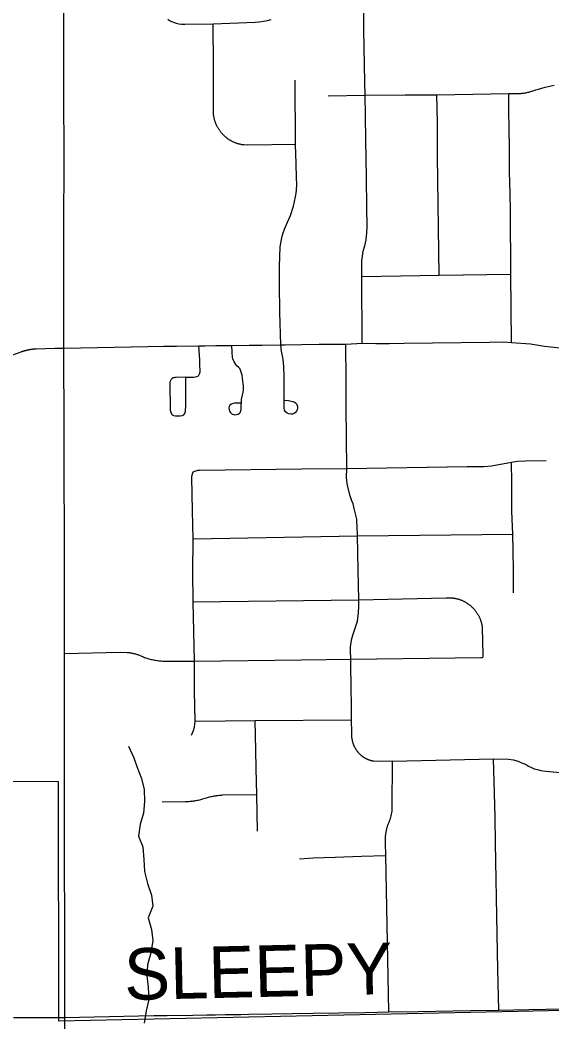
# Model space of a CAD drawing. Extents: x 0 to 34, y 0 to 22.
# Drawn here: x 5.217 to 5.51, y 18.387 to 18.939 of the extents above; entities that cross this region are included whole.
import ezdxf

# ---------------------------------------------------------------- set-up
doc = ezdxf.new("R2010")
doc.units = 0
for name, color, linetype in [('GM_X_City_Street', 7, 'Continuous'), ('GM_X_Corporation', 7, 'Continuous'), ('GM_X_County_Road', 7, 'Continuous'), ('GM_X_County_Road_Text', 7, 'Continuous'), ('GM_X_Minor_River', 7, 'Continuous'), ('GM_X_Township_Road', 7, 'Continuous'), ('GM_X_US_Route', 7, 'Continuous')]:
    doc.layers.add(name, color=color, linetype=linetype)

msp = doc.modelspace()

# ---------------------------------------------------------------- linework, layer by layer
at = {"layer": 'GM_X_City_Street'}
for points in [[(5.40551, 18.76131), (5.40524, 18.79805), (5.40537, 18.8068), (5.40561, 18.80931), (5.4061, 18.81213), (5.4069, 18.81494), (5.40763, 18.81825), (5.40812, 18.82222), (5.40818, 18.82565), (5.40806, 18.83618), (5.40781, 18.8527), (5.40751, 18.87351), (5.40732, 18.88666), (5.40708, 18.89798), (5.4069, 18.90527), (5.40658, 18.92473), (5.40648, 18.93418), (5.40639, 18.94387)], [(5.29832, 18.93986), (5.29936, 18.93926), (5.30044, 18.9387), (5.30152, 18.93826), (5.303, 18.93774), (5.30448, 18.93738), (5.30596, 18.93718), (5.30784, 18.9371), (5.3234, 18.93746), (5.34659, 18.93826), (5.3488, 18.93848), (5.35118, 18.9388), (5.35333, 18.93922), (5.35532, 18.93967)], [(5.36881, 18.87083), (5.34251, 18.87051), (5.3402, 18.87063), (5.33987, 18.87067), (5.33954, 18.87072), (5.33922, 18.87077), (5.33889, 18.87082), (5.33857, 18.87089), (5.33824, 18.87096), (5.33792, 18.87103), (5.3376, 18.87111), (5.33728, 18.8712), (5.33697, 18.87129), (5.33666, 18.87139), (5.33634, 18.87149), (5.33604, 18.8716), (5.33573, 18.87172), (5.33543, 18.87184), (5.33512, 18.87197), (5.33483, 18.8721), (5.33453, 18.87223), (5.33423, 18.87238), (5.33394, 18.87252), (5.33365, 18.87268), (5.33336, 18.87283), (5.33307, 18.873), (5.33279, 18.87316), (5.3325, 18.87333), (5.33223, 18.87351), (5.33195, 18.87369), (5.33168, 18.87388), (5.3314, 18.87407), (5.33114, 18.87426), (5.33088, 18.87446), (5.33062, 18.87467), (5.33036, 18.87488), (5.33011, 18.87509), (5.32986, 18.87531), (5.32961, 18.87553), (5.32937, 18.87576), (5.32913, 18.87599), (5.3289, 18.87622), (5.32867, 18.87646), (5.32844, 18.87671), (5.32822, 18.87695), (5.32801, 18.8772), (5.32779, 18.87746), (5.32758, 18.87771), (5.32738, 18.87798), (5.32718, 18.87824), (5.32699, 18.87851), (5.3268, 18.87878), (5.32661, 18.87906), (5.32643, 18.87934), (5.32626, 18.87962), (5.32609, 18.87991), (5.32592, 18.88019), (5.32576, 18.88048), (5.3256, 18.88078), (5.32546, 18.88107), (5.32531, 18.88137), (5.32517, 18.88167), (5.32504, 18.88198), (5.32491, 18.88228), (5.32478, 18.88259), (5.32466, 18.8829), (5.32455, 18.88321), (5.32444, 18.88353), (5.32434, 18.88384), (5.32425, 18.88416), (5.32415, 18.88448), (5.32407, 18.8848), (5.32399, 18.88512), (5.32392, 18.88545), (5.32385, 18.88577), (5.32378, 18.8861), (5.32373, 18.88643), (5.32368, 18.88675), (5.32363, 18.88708), (5.32359, 18.88741), (5.32356, 18.88774), (5.32353, 18.91439), (5.3234, 18.93746)], [(5.36062, 18.76042), (5.3602, 18.77853), (5.35997, 18.79382), (5.35992, 18.80368), (5.36038, 18.8145), (5.36107, 18.81855), (5.36185, 18.82163), (5.36272, 18.82425), (5.36433, 18.8281), (5.36593, 18.83177), (5.36763, 18.83687), (5.36874, 18.84196), (5.36912, 18.8441), (5.36932, 18.84577), (5.36947, 18.84885), (5.36933, 18.85256), (5.36905, 18.86043), (5.36881, 18.87083), (5.36862, 18.90632)], [(5.3867, 18.89772), (5.40708, 18.89798), (5.42913, 18.89826), (5.44661, 18.89823), (5.48627, 18.89895), (5.49121, 18.8989), (5.49178, 18.89893), (5.49234, 18.89897), (5.49291, 18.89902), (5.49347, 18.89908), (5.49403, 18.89915), (5.49459, 18.89923), (5.49515, 18.89931), (5.4957, 18.89941), (5.49626, 18.89952), (5.49681, 18.89963), (5.49736, 18.89976), (5.49791, 18.8999), (5.49846, 18.90004), (5.499, 18.9002), (5.49954, 18.90036), (5.50008, 18.90054), (5.50061, 18.90072), (5.50124, 18.90091), (5.5026, 18.90138), (5.50445, 18.9019), (5.50639, 18.9024), (5.5096, 18.9032), (5.51126, 18.90362)], [(5.44791, 18.79877), (5.44701, 18.86421), (5.44693, 18.88306), (5.44661, 18.89823)], [(5.48785, 18.76175), (5.48733, 18.79936), (5.48736, 18.80992), (5.48723, 18.82363), (5.48718, 18.83414), (5.48697, 18.84402), (5.48676, 18.85571), (5.48663, 18.8685), (5.48655, 18.88038), (5.48639, 18.88892), (5.48632, 18.89493), (5.48627, 18.89895)], [(5.40524, 18.79805), (5.44791, 18.79877), (5.48733, 18.79936)], [(5.30826, 18.74267), (5.303, 18.74249), (5.30258, 18.74245), (5.30221, 18.7424), (5.30184, 18.74233), (5.30151, 18.74226), (5.30123, 18.74218), (5.30102, 18.74211), (5.3008, 18.74197), (5.30059, 18.74182), (5.30036, 18.74154), (5.30021, 18.74133), (5.30006, 18.74108), (5.29993, 18.74084), (5.2998, 18.74055), (5.29967, 18.74025), (5.2996, 18.73995), (5.29956, 18.73967), (5.29967, 18.72444), (5.30002, 18.72313), (5.30081, 18.72194), (5.3016, 18.72145), (5.30259, 18.72128), (5.30522, 18.72131), (5.30642, 18.72155), (5.30716, 18.72194), (5.30778, 18.72264), (5.30809, 18.72385), (5.3082, 18.72457), (5.30831, 18.72637), (5.30826, 18.74267), (5.3128, 18.74272), (5.31436, 18.74295), (5.31532, 18.74345), (5.31592, 18.74446), (5.31615, 18.74552), (5.31606, 18.75006), (5.31596, 18.75213), (5.31583, 18.75461), (5.31555, 18.75984)], [(5.33848, 18.72834), (5.336, 18.72839), (5.33513, 18.72829), (5.33435, 18.72806), (5.33348, 18.72774), (5.33265, 18.72715), (5.33224, 18.72655), (5.3321, 18.72568), (5.33215, 18.7249), (5.33238, 18.72398), (5.3327, 18.72329), (5.33325, 18.72274), (5.33389, 18.72233), (5.33472, 18.7221), (5.33541, 18.72196), (5.33711, 18.72215), (5.33798, 18.72279), (5.33839, 18.72334), (5.33867, 18.72426), (5.33873, 18.72483), (5.33877, 18.72544), (5.33899, 18.73027), (5.33995, 18.73435), (5.34017, 18.73586), (5.34009, 18.73777), (5.33958, 18.74195), (5.33928, 18.74375), (5.3389, 18.74543), (5.33851, 18.74646), (5.33799, 18.74732), (5.33734, 18.7481), (5.33663, 18.74868), (5.33588, 18.74953), (5.33495, 18.7511), (5.33429, 18.7527), (5.33409, 18.75356), (5.33389, 18.75647), (5.33375, 18.76006)], [(5.36289, 18.73003), (5.36488, 18.72972), (5.3664, 18.72941), (5.36719, 18.72924), (5.36795, 18.72896), (5.36874, 18.72845), (5.36929, 18.72789), (5.36967, 18.72707), (5.36985, 18.72638), (5.36988, 18.72587), (5.36983, 18.72527), (5.36972, 18.72481), (5.36945, 18.72417), (5.36927, 18.72386), (5.36874, 18.72314), (5.36795, 18.72256), (5.36702, 18.72225), (5.36609, 18.72218), (5.36512, 18.72239), (5.36419, 18.7228), (5.36333, 18.72359), (5.36278, 18.72445), (5.36251, 18.72559), (5.36258, 18.72762), (5.36254, 18.7334), (5.36247, 18.73874), (5.36254, 18.74307), (5.36237, 18.74858), (5.36199, 18.75264), (5.3611, 18.75698), (5.36062, 18.76042)], [(5.42212, 18.53096), (5.41424, 18.53083), (5.41172, 18.531), (5.41147, 18.53104), (5.41123, 18.53108), (5.41099, 18.53113), (5.41075, 18.53118), (5.41051, 18.53124), (5.41028, 18.5313), (5.41004, 18.53137), (5.40981, 18.53144), (5.40957, 18.53152), (5.40934, 18.5316), (5.40911, 18.53168), (5.40888, 18.53177), (5.40865, 18.53186), (5.40843, 18.53195), (5.4082, 18.53205), (5.40798, 18.53216), (5.40776, 18.53226), (5.40754, 18.53238), (5.40733, 18.53249), (5.40712, 18.53261), (5.4069, 18.53273), (5.40669, 18.53286), (5.40649, 18.53299), (5.40628, 18.53313), (5.40608, 18.53326), (5.40588, 18.53341), (5.40568, 18.53355), (5.40549, 18.5337), (5.4053, 18.53385), (5.40511, 18.53401), (5.40492, 18.53417), (5.40473, 18.53433), (5.40455, 18.5345), (5.40437, 18.53467), (5.4042, 18.53484), (5.40402, 18.53502), (5.40385, 18.53519), (5.40368, 18.53538), (5.40352, 18.53556), (5.40336, 18.53575), (5.4032, 18.53594), (5.40304, 18.53613), (5.40289, 18.53633), (5.40274, 18.53653), (5.4026, 18.53673), (5.40246, 18.53693), (5.40232, 18.53714), (5.40218, 18.53735), (5.40205, 18.53756), (5.40192, 18.53778), (5.40179, 18.53799), (5.40167, 18.53821), (5.40155, 18.53843), (5.40144, 18.53865), (5.40133, 18.53888), (5.40122, 18.5391), (5.40112, 18.53933), (5.40102, 18.53956), (5.40092, 18.53979), (5.40083, 18.54003), (5.40074, 18.54026), (5.40066, 18.54049), (5.40058, 18.54073), (5.4005, 18.54097), (5.40043, 18.54121), (5.40036, 18.54145), (5.4003, 18.5417), (5.40023, 18.54194), (5.40018, 18.54218), (5.40013, 18.54243), (5.40008, 18.54268), (5.40003, 18.54292), (5.39999, 18.54317), (5.39982, 18.54447), (5.39972, 18.54681), (5.39965, 18.55379), (5.39958, 18.56192), (5.39934, 18.57149), (5.39927, 18.58448), (5.39927, 18.58717), (5.39911, 18.59225), (5.39914, 18.59411), (5.39935, 18.59621), (5.39959, 18.59786), (5.40027, 18.60052), (5.40156, 18.60421), (5.40288, 18.60819), (5.4035, 18.61272), (5.40368, 18.61627), (5.40368, 18.62), (5.40325, 18.6364), (5.4029, 18.65512), (5.40279, 18.66065), (5.40264, 18.66284), (5.40246, 18.66436), (5.40202, 18.66656), (5.40171, 18.668), (5.40117, 18.67025), (5.40045, 18.67273), (5.39977, 18.67456), (5.39887, 18.67714), (5.3974, 18.68298), (5.39693, 18.68708), (5.397, 18.69237), (5.39688, 18.70926), (5.39675, 18.72639), (5.39664, 18.741), (5.39649, 18.76091)], [(5.31235, 18.69044), (5.3138, 18.69104), (5.31453, 18.69125), (5.31491, 18.6913), (5.31581, 18.69137), (5.37216, 18.69213), (5.397, 18.69237), (5.46341, 18.69332), (5.47248, 18.69346), (5.47671, 18.69377), (5.48584, 18.69536), (5.48782, 18.69575), (5.49117, 18.69638), (5.4954, 18.6966), (5.50679, 18.69679)], [(5.48895, 18.62375), (5.4889, 18.63274), (5.48886, 18.63616), (5.48864, 18.64706), (5.48846, 18.65612), (5.488, 18.66879), (5.4879, 18.68446), (5.48782, 18.69575)], [(5.31138, 18.54532), (5.31248, 18.54782), (5.31311, 18.54971), (5.31337, 18.55122), (5.31354, 18.55308), (5.31314, 18.56952), (5.31302, 18.58011), (5.31302, 18.58611), (5.31233, 18.61882), (5.31214, 18.63499), (5.31228, 18.65356), (5.31197, 18.66898), (5.31169, 18.68749), (5.31179, 18.68885), (5.31235, 18.69044)], [(5.31228, 18.65356), (5.4029, 18.65512), (5.48846, 18.65612)], [(5.31233, 18.61882), (5.40368, 18.62), (5.45176, 18.62102), (5.45539, 18.62095), (5.45571, 18.62091), (5.45603, 18.62086), (5.45635, 18.62081), (5.45667, 18.62075), (5.45699, 18.62069), (5.45731, 18.62062), (5.45762, 18.62055), (5.45794, 18.62047), (5.45825, 18.62038), (5.45856, 18.62029), (5.45887, 18.62019), (5.45918, 18.62009), (5.45948, 18.61999), (5.45979, 18.61987), (5.46009, 18.61976), (5.46039, 18.61964), (5.46069, 18.61951), (5.46099, 18.61937), (5.46128, 18.61923), (5.46157, 18.61909), (5.46186, 18.61894), (5.46214, 18.61879), (5.46243, 18.61863), (5.46271, 18.61847), (5.46299, 18.6183), (5.46326, 18.61813), (5.46353, 18.61795), (5.4638, 18.61776), (5.46406, 18.61758), (5.46433, 18.61739), (5.46458, 18.61719), (5.46484, 18.61699), (5.46509, 18.61678), (5.46534, 18.61657), (5.46558, 18.61636), (5.46582, 18.61614), (5.46606, 18.61592), (5.46629, 18.6157), (5.46652, 18.61546), (5.46674, 18.61523), (5.46696, 18.61499), (5.46718, 18.61475), (5.46739, 18.6145), (5.4676, 18.61425), (5.4678, 18.614), (5.468, 18.61374), (5.4682, 18.61348), (5.46839, 18.61322), (5.46857, 18.61296), (5.46875, 18.61269), (5.46893, 18.61241), (5.46909, 18.61214), (5.46926, 18.61186), (5.46942, 18.61158), (5.46958, 18.61129), (5.46973, 18.611), (5.46987, 18.61072), (5.47002, 18.61042), (5.47015, 18.61013), (5.47028, 18.60983), (5.47041, 18.60953), (5.47053, 18.60923), (5.47064, 18.60893), (5.47075, 18.60862), (5.47086, 18.60831), (5.47096, 18.60801), (5.47105, 18.6077), (5.47114, 18.60738), (5.47122, 18.60707), (5.4713, 18.60675), (5.47137, 18.60644), (5.47143, 18.60612), (5.4715, 18.6058), (5.47155, 18.60548), (5.4716, 18.60516), (5.47164, 18.60484), (5.47168, 18.60452), (5.47199, 18.58936), (5.47191, 18.58827)], [(5.2415, 18.5904), (5.27218, 18.59099), (5.27604, 18.59095), (5.27647, 18.59091), (5.27689, 18.59086), (5.27732, 18.59081), (5.27774, 18.59074), (5.27817, 18.59067), (5.27859, 18.5906), (5.27901, 18.59051), (5.27943, 18.59042), (5.27985, 18.59032), (5.28026, 18.59021), (5.28067, 18.59009), (5.28109, 18.58997), (5.2815, 18.58984), (5.2819, 18.5897), (5.28231, 18.58956), (5.28271, 18.58941), (5.28311, 18.58925), (5.2835, 18.58909), (5.2839, 18.58892), (5.28429, 18.58874), (5.28496, 18.58841), (5.28556, 18.58819), (5.28615, 18.58799), (5.28675, 18.58779), (5.28736, 18.5876), (5.28796, 18.58743), (5.28857, 18.58726), (5.28919, 18.58711), (5.2898, 18.58696), (5.29042, 18.58683), (5.29104, 18.58671), (5.29166, 18.58659), (5.29228, 18.58649), (5.29291, 18.5864), (5.29354, 18.58633), (5.29417, 18.58626), (5.29479, 18.5862), (5.29542, 18.58616), (5.29606, 18.58612), (5.31302, 18.58611), (5.37213, 18.5869), (5.39927, 18.58717), (5.45671, 18.58786), (5.47085, 18.58805), (5.47155, 18.5881), (5.47191, 18.58827)], [(5.31354, 18.55308), (5.34657, 18.55337), (5.39965, 18.55379)], [(5.34775, 18.49247), (5.34737, 18.51258), (5.34712, 18.52686), (5.34694, 18.53704), (5.34657, 18.55337)], [(5.42212, 18.53096), (5.47794, 18.53233), (5.4862, 18.53213), (5.48882, 18.53172), (5.48934, 18.53153), (5.49139, 18.53091), (5.49325, 18.53016), (5.49549, 18.5293), (5.49711, 18.52831), (5.49883, 18.52745), (5.50024, 18.52682), (5.50206, 18.52634), (5.50392, 18.5259), (5.50678, 18.52547), (5.51276, 18.52486), (5.5153, 18.52471), (5.52477, 18.52451), (5.5373, 18.52483), (5.5448, 18.52481)], [(5.48072, 18.39383), (5.48022, 18.41609), (5.47979, 18.43561), (5.47895, 18.48593), (5.47872, 18.49988), (5.4784, 18.51337), (5.47794, 18.53233)], [(5.42027, 18.39288), (5.41847, 18.47893), (5.41834, 18.48598), (5.41842, 18.48992), (5.41847, 18.49038), (5.41853, 18.49083), (5.41859, 18.49129), (5.41866, 18.49174), (5.41874, 18.49219), (5.41883, 18.49264), (5.41893, 18.49309), (5.41903, 18.49354), (5.41914, 18.49398), (5.41926, 18.49442), (5.41939, 18.49486), (5.41952, 18.4953), (5.41966, 18.49574), (5.41981, 18.49617), (5.41997, 18.4966), (5.42013, 18.49703), (5.4203, 18.49745), (5.42048, 18.49787), (5.42067, 18.49829), (5.42094, 18.49905), (5.42107, 18.49944), (5.42151, 18.50093), (5.42193, 18.50337), (5.4221, 18.50519), (5.42212, 18.53096)], [(5.29528, 18.50857), (5.30799, 18.50873), (5.30997, 18.50881), (5.31064, 18.50886), (5.31129, 18.50892), (5.31195, 18.509), (5.31261, 18.50908), (5.31326, 18.50918), (5.31391, 18.50929), (5.31456, 18.50941), (5.31521, 18.50954), (5.31586, 18.50969), (5.3165, 18.50984), (5.31714, 18.51001), (5.31777, 18.51019), (5.31897, 18.51056), (5.32018, 18.51094), (5.32081, 18.51111), (5.32145, 18.51128), (5.32208, 18.51144), (5.32272, 18.51159), (5.32336, 18.51172), (5.32401, 18.51184), (5.32466, 18.51195), (5.32531, 18.51205), (5.32596, 18.51214), (5.32661, 18.51222), (5.32726, 18.51229), (5.32792, 18.51234), (5.32858, 18.51238), (5.34737, 18.51258)], [(5.37092, 18.47722), (5.37846, 18.47776), (5.39069, 18.47815), (5.40513, 18.47864), (5.41847, 18.47893)]]:
    msp.add_lwpolyline(points, dxfattribs=at)
at = {"layer": 'GM_X_Corporation'}
msp.add_lwpolyline([(5.73568, 18.39826), (5.4827, 18.39283), (5.23837, 18.38777), (5.23824, 18.51969), (5.07403, 18.51973)], dxfattribs=at)
at = {"layer": 'GM_X_County_Road'}
for points in [[(5.48072, 18.39383), (5.49729, 18.39416), (5.51639, 18.39445), (5.52847, 18.39476), (5.53971, 18.39515), (5.54581, 18.39535)], [(5.24163, 18.38972), (5.28224, 18.39064), (5.29075, 18.39075), (5.29801, 18.39084), (5.31209, 18.39103), (5.31988, 18.39113), (5.32468, 18.39119), (5.33015, 18.3913), (5.33435, 18.39137), (5.33867, 18.39145), (5.34305, 18.39153), (5.35575, 18.39177), (5.37845, 18.39214), (5.40721, 18.39251), (5.42027, 18.39288), (5.43626, 18.39304), (5.46531, 18.39361), (5.48072, 18.39383)]]:
    msp.add_lwpolyline(points, dxfattribs=at)
at = {"layer": 'GM_X_Minor_River'}
msp.add_lwpolyline([(5.27682, 18.5393), (5.27962, 18.53291), (5.28124, 18.52802), (5.28385, 18.52143), (5.28531, 18.5154), (5.28547, 18.50876), (5.28505, 18.5023), (5.28311, 18.49618), (5.28231, 18.48971), (5.28472, 18.48369), (5.28525, 18.47688), (5.2856, 18.47024), (5.28726, 18.46364), (5.28949, 18.45705), (5.2902, 18.45099), (5.28751, 18.44467), (5.28936, 18.43826), (5.29006, 18.43221), (5.28908, 18.42535), (5.28716, 18.41867), (5.28692, 18.41259), (5.28763, 18.40634), (5.28797, 18.39971), (5.28642, 18.39341), (5.28544, 18.38656)], dxfattribs=at)
at = {"layer": 'GM_X_Township_Road'}
for points in [[(5.20463, 18.75192), (5.21753, 18.75662), (5.21759, 18.75664), (5.21764, 18.75666), (5.21768, 18.75668), (5.21773, 18.75669), (5.21777, 18.75671), (5.21782, 18.75672), (5.21786, 18.75674), (5.21791, 18.75676), (5.21795, 18.75677), (5.218, 18.75679), (5.21804, 18.7568), (5.21809, 18.75682), (5.21813, 18.75683), (5.21818, 18.75685), (5.21822, 18.75686), (5.21827, 18.75688), (5.21831, 18.75689), (5.21836, 18.75691), (5.2184, 18.75692), (5.21845, 18.75694), (5.21849, 18.75695), (5.21854, 18.75697), (5.21858, 18.75698), (5.21863, 18.757), (5.21867, 18.75701), (5.21872, 18.75702), (5.21876, 18.75704), (5.21881, 18.75705), (5.21885, 18.75707), (5.2189, 18.75708), (5.21894, 18.75709), (5.21899, 18.75711), (5.21903, 18.75712), (5.21908, 18.75713), (5.21912, 18.75715), (5.21917, 18.75716), (5.21921, 18.75718), (5.21926, 18.75719), (5.21931, 18.7572), (5.21935, 18.75722), (5.2194, 18.75723), (5.21944, 18.75724), (5.21949, 18.75726), (5.21953, 18.75727), (5.21958, 18.75728), (5.21962, 18.75729), (5.21967, 18.75731), (5.21972, 18.75732), (5.21976, 18.75733), (5.21981, 18.75734), (5.21985, 18.75736), (5.2199, 18.75737), (5.21994, 18.75738), (5.21999, 18.75739), (5.22004, 18.75741), (5.22008, 18.75742), (5.22013, 18.75743), (5.22017, 18.75744), (5.22022, 18.75745), (5.22027, 18.75746), (5.22031, 18.75748), (5.22036, 18.75749), (5.2204, 18.7575), (5.22045, 18.75751), (5.22049, 18.75752), (5.22054, 18.75753), (5.22059, 18.75755), (5.22063, 18.75755), (5.22068, 18.75757), (5.22073, 18.75758), (5.22077, 18.75759), (5.22082, 18.7576), (5.22086, 18.75761), (5.22091, 18.75762), (5.22096, 18.75763), (5.221, 18.75764), (5.22105, 18.75765), (5.22109, 18.75766), (5.22114, 18.75767), (5.22119, 18.75768), (5.22123, 18.75769), (5.22128, 18.7577), (5.22133, 18.75771), (5.22137, 18.75772), (5.22142, 18.75773), (5.22147, 18.75774), (5.22151, 18.75775), (5.22156, 18.75776), (5.22161, 18.75777), (5.22165, 18.75778), (5.2217, 18.75779), (5.22174, 18.7578), (5.22179, 18.75781), (5.22184, 18.75782), (5.22188, 18.75783), (5.22193, 18.75783), (5.22198, 18.75784), (5.22202, 18.75785), (5.22207, 18.75786), (5.22212, 18.75787), (5.22216, 18.75788), (5.22221, 18.75789), (5.22226, 18.7579), (5.2223, 18.75791), (5.22235, 18.75791), (5.22239, 18.75792), (5.22244, 18.75793), (5.22249, 18.75794), (5.22253, 18.75795), (5.22258, 18.75795), (5.22263, 18.75796), (5.22267, 18.75797), (5.22272, 18.75797), (5.22277, 18.75798), (5.22282, 18.75799), (5.22286, 18.758), (5.22291, 18.758), (5.22296, 18.75801), (5.223, 18.75802), (5.22305, 18.75803), (5.2231, 18.75803), (5.22314, 18.75804), (5.22319, 18.75805), (5.22324, 18.75805), (5.22328, 18.75806), (5.22333, 18.75807), (5.22338, 18.75807), (5.22343, 18.75808), (5.22347, 18.75809), (5.22352, 18.75809), (5.22357, 18.7581), (5.22361, 18.7581), (5.22366, 18.75811), (5.22371, 18.75812), (5.22376, 18.75812), (5.2238, 18.75813), (5.22385, 18.75814), (5.2239, 18.75814), (5.22394, 18.75814), (5.22399, 18.75815), (5.22404, 18.75816), (5.22408, 18.75816), (5.22413, 18.75817), (5.22418, 18.75817), (5.22422, 18.75818), (5.22427, 18.75818), (5.22432, 18.75819), (5.22437, 18.75819), (5.22441, 18.7582), (5.22446, 18.7582), (5.22451, 18.75821), (5.22455, 18.75821), (5.2246, 18.75822), (5.22465, 18.75822), (5.2247, 18.75823), (5.22474, 18.75823), (5.22479, 18.75823), (5.22484, 18.75824), (5.22489, 18.75824), (5.22493, 18.75824), (5.22498, 18.75825), (5.22503, 18.75825), (5.22507, 18.75826), (5.22512, 18.75826), (5.22517, 18.75826), (5.22522, 18.75827), (5.22526, 18.75827), (5.22592, 18.75831), (5.23623, 18.75857), (5.24109, 18.75864)], [(5.24109, 18.75864), (5.28747, 18.75958), (5.29608, 18.75968)], [(5.29608, 18.75968), (5.30317, 18.75977), (5.31555, 18.75984), (5.31879, 18.75995), (5.3248, 18.76002), (5.32828, 18.76007), (5.3312, 18.76011), (5.33375, 18.76006), (5.34314, 18.76026), (5.3472, 18.76031), (5.35031, 18.76035), (5.36062, 18.76042), (5.3626, 18.76051), (5.37218, 18.76064), (5.38175, 18.76076), (5.38496, 18.7608), (5.39649, 18.76091), (5.40551, 18.76131), (5.41308, 18.76116), (5.4205, 18.76126), (5.42863, 18.76137), (5.44426, 18.76157), (5.47563, 18.76197), (5.48353, 18.76207), (5.48785, 18.76175), (5.49827, 18.76095), (5.50599, 18.75975), (5.51636, 18.75864)], [(5.21335, 18.38971), (5.24163, 18.38972)]]:
    msp.add_lwpolyline(points, dxfattribs=at)
at = {"layer": 'GM_X_US_Route'}
msp.add_line((5.24135, 18.68303), (5.24125, 18.71357), dxfattribs=at)
for points in [[(5.24125, 18.71357), (5.24109, 18.75864), (5.24115, 18.82057), (5.24123, 18.86718), (5.24111, 18.89623), (5.24104, 18.91014), (5.2411, 18.96116), (5.24049, 18.98052), (5.24081, 19.00134), (5.24091, 19.03485), (5.24144, 19.08975), (5.24132, 19.1067)], [(5.24146, 18.62513), (5.24141, 18.66392), (5.24136, 18.68129), (5.24135, 18.68303)], [(5.2415, 18.52776), (5.2415, 18.5904), (5.24146, 18.62513)], [(5.24163, 18.38972), (5.2415, 18.52753), (5.2415, 18.52776)], [(5.24014, 17.86435), (5.23996, 17.88547), (5.24001, 17.89931), (5.24, 17.90343), (5.23996, 17.92179), (5.23992, 17.94227), (5.23998, 17.95984), (5.24002, 17.97041), (5.24011, 17.99394), (5.24014, 18.00177), (5.24022, 18.0225), (5.24038, 18.06668), (5.24044, 18.08249), (5.24054, 18.10767), (5.24062, 18.12803), (5.24053, 18.1584), (5.24088, 18.19015), (5.24097, 18.2117), (5.24105, 18.23079), (5.24114, 18.25217), (5.24119, 18.2645), (5.24123, 18.27319), (5.24163, 18.38972)]]:
    msp.add_lwpolyline(points, dxfattribs=at)

# ---------------------------------------------------------------- texts
at = {"layer": 'GM_X_County_Road_Text'}
msp.add_text('SLEEPY', height=0.028409, rotation=1.3105, dxfattribs=at).set_placement((5.27461, 18.3993))

doc.saveas('drawing.dxf')
